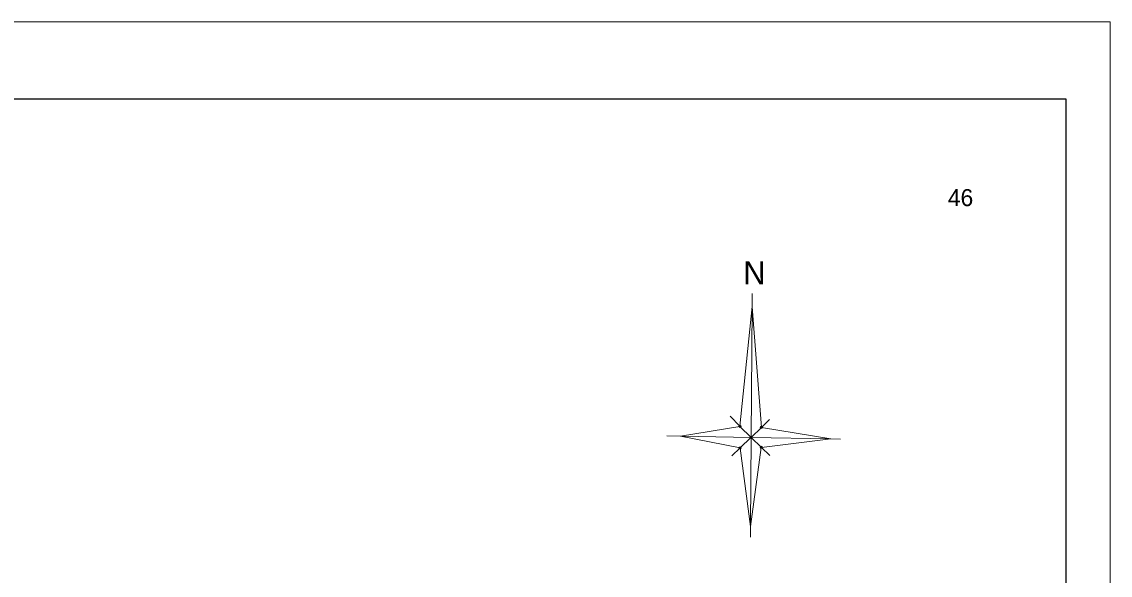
# Model space of a CAD drawing. Extents: x 854879 to 917879, y 8541948 to 8631048.
# Drawn here: x 882670 to 917879, y 8613149 to 8631048 of the extents above; entities that cross this region are included whole.
import ezdxf
from ezdxf.enums import TextEntityAlignment as Align

# ---------------------------------------------------------------- set-up
doc = ezdxf.new("R2010")
doc.units = 0
doc.header["$LTSCALE"] = 150
doc.header["$PDMODE"] = 32
doc.header["$PDSIZE"] = 75
for name, color, linetype, lineweight in [('18', 7, 'Continuous', 13), ('36', 7, 'Continuous', 13), ('44', 7, 'Continuous', 13), ('50', 7, 'Continuous', 13), ('59', 7, 'Continuous', 13)]:
    doc.layers.add(name, color=color, linetype=linetype, lineweight=lineweight)
doc.layers.add('61', color=7, linetype='Continuous')

msp = doc.modelspace()

# ---------------------------------------------------------------- linework, layer by layer
at = {"layer": '18'}
msp.add_lwpolyline([(858846.4, 8601455.3), (858846.4, 8628560.7), (916445.6, 8628560.7), (916445.6, 8586757.5), (916451.2, 8586745.1)], dxfattribs=at)
at = {"layer": '36'}
msp.add_lwpolyline([(854878.6, 8541948.4), (917878.6, 8541948.4), (917878.6, 8631048.4), (854878.6, 8631048.4)], close=True, dxfattribs=at)
at = {"layer": '36', "lineweight": 25}
msp.add_lwpolyline([(858846.4, 8628560.7), (916445.6, 8628560.7), (916445.6, 8544954.2), (858846.4, 8544954.2)], close=True, dxfattribs=at)
at = {"layer": '44'}
msp.add_lwpolyline([(858846.4, 8628560.7), (916445.6, 8628560.7), (916445.6, 8544954.2), (858846.4, 8544954.2)], close=True, dxfattribs=at)
at = {"layer": '50'}
for p, q in [((906295.5, 8621837.1), (906298.4, 8622258.6)), ((906596.1, 8617928.8), (906295.8, 8621833.7)), ((905897.9, 8617964.3), (903976.1, 8617650.2)), ((905899, 8617965.3), (905580, 8618290.3)), ((906262.4, 8617608.1), (905900.3, 8617964)), ((906599.2, 8617931.8), (906860, 8618187.2)), ((903973.6, 8617649.9), (903537.4, 8617658)), ((906262.3, 8617608.7), (906593.2, 8617925.9)), ((908844.8, 8617559.6), (906265, 8617607.4)), ((906601.7, 8617927.8), (908845.8, 8617559.6)), ((905638.7, 8617010.7), (905903.5, 8617264.6)), ((906245.7, 8614726.9), (905906.2, 8617260.4)), ((905907, 8617268), (906258.5, 8617605.1)), ((906862.7, 8617018.1), (906594.7, 8617281.5)), ((906595.6, 8617281.8), (908845.5, 8617559.4)), ((909154.2, 8617553.8), (908845.6, 8617559.5)), ((906243.9, 8614375.3), (906246.3, 8614723))]:
    msp.add_line(p, q, dxfattribs=at)
for points in [[(905899.9, 8617966.4), (906295.5, 8621837.8), (906295.5, 8621837.2)], [(906295.5, 8621835.1), (906266.2, 8617607.4), (906262.3, 8617608.7)], [(905905.1, 8617268.6), (903974.6, 8617649.9), (903974.7, 8617649.9)], [(903977.6, 8617649.9), (906262, 8617607.5), (906262.4, 8617608.1)], [(906263.4, 8617607.1), (906594.2, 8617281.9), (906595.6, 8617281.8)], [(906266.2, 8617601.9), (906246.3, 8614724.7), (906245.7, 8614726.9)], [(906594.5, 8617281.6), (906592.6, 8617281.4), (906246.3, 8614722.5), (906246.2, 8614723.3)]]:
    msp.add_lwpolyline(points, dxfattribs=at)
for p in [(905899.7, 8617964.6), (906596.1, 8617928.8), (905905.1, 8617268.6), (906592.6, 8617281.4)]:
    msp.add_point(p, dxfattribs=at)

# ---------------------------------------------------------------- texts
at = {"layer": '59'}
msp.add_text('N', height=750, dxfattribs=at).set_placement((906369.1, 8622553.1), align=Align.CENTER)
at = {"layer": '61'}
msp.add_text('46', height=550, dxfattribs=at).set_placement((913037.5, 8625086.7), align=Align.CENTER)

doc.saveas('drawing.dxf')
